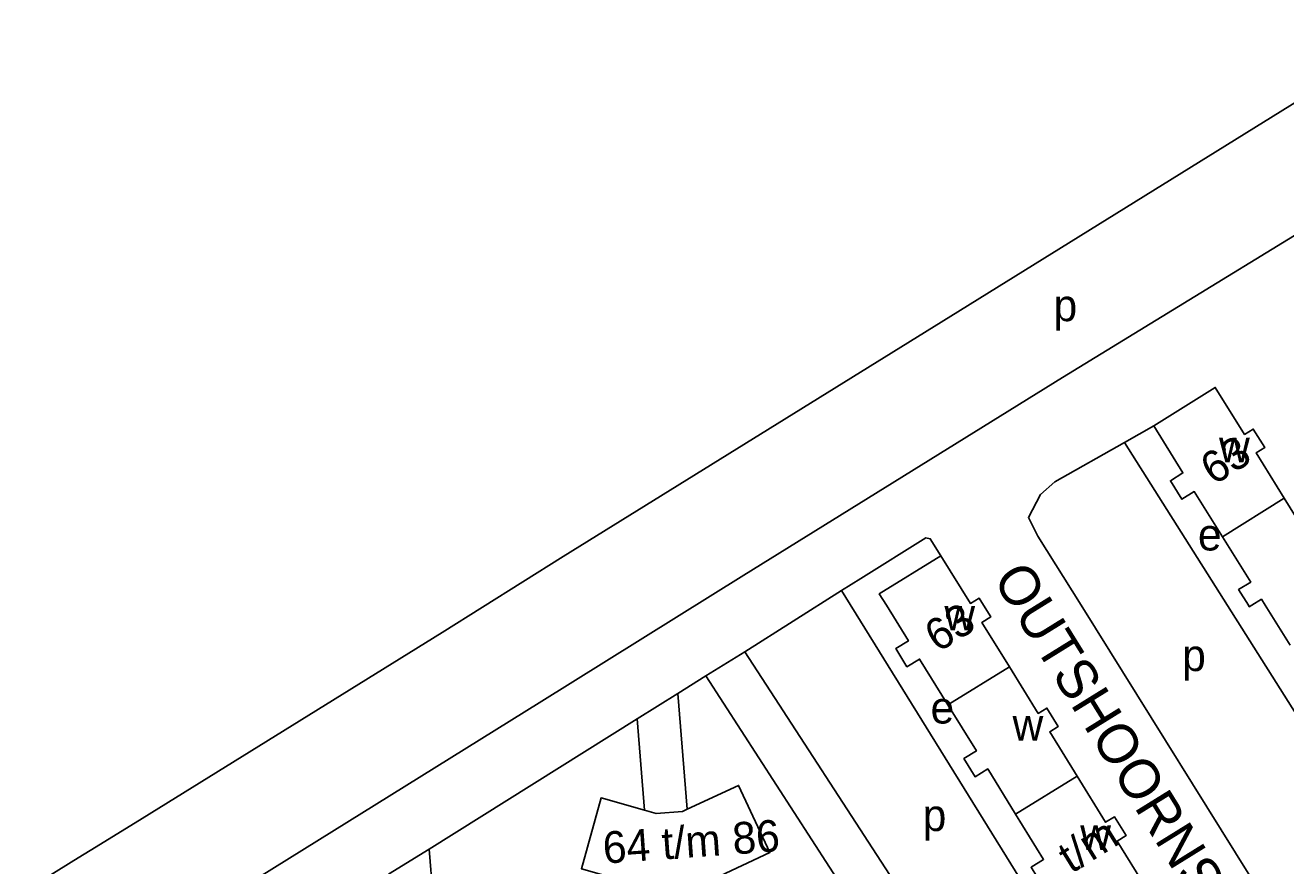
# Model space of a CAD drawing. Extents: x 159294 to 161936, y 384538 to 386517.
# Drawn here: x 160068.5 to 160227.2, y 386133.9 to 386239.7 of the extents above; entities that cross this region are included whole.
import ezdxf

# ---------------------------------------------------------------- set-up
doc = ezdxf.new("R2010")
doc.units = 0
for name, color, linetype in [('BLT_Basislijn', 7, 'Continuous'), ('BLT_Bebouwing', 7, 'Continuous'), ('BLT_Centroide', 7, 'Continuous'), ('BLT_Huisnummer_reeks', 7, 'Continuous'), ('BLT_Onderverdeling_panden', 7, 'Continuous'), ('BLT_Straatnaam', 7, 'Continuous')]:
    doc.layers.add(name, color=color, linetype=linetype)

msp = doc.modelspace()

# ---------------------------------------------------------------- linework, layer by layer
at = {"layer": 'BLT_Basislijn'}
for p, q in [((160206.88, 386187.16), (160243.71, 386128.83)), ((160171.29, 386168.51), (160209.94, 386106.13)), ((160121.03, 386163.25), (160083.26, 386139.84)), ((160159.1, 386160.81), (160154.21, 386157.79)), ((160159.1, 386160.81), (160182.3, 386125.13)), ((160150.67, 386155.55), (160154.21, 386157.79)), ((160154.21, 386157.79), (160177.14, 386122.35)), ((160150.67, 386155.55), (160145.55, 386152.35)), ((160151.86, 386140.99), (160150.67, 386155.55)), ((160145.55, 386152.35), (160119.37, 386135.95)), ((160145.55, 386152.35), (160146.5, 386140.86)), ((160083.26, 386139.84), (160078.01, 386136.59)), ((160078.01, 386136.59), (160074.68, 386134.53)), ((160114.28, 386132.8), (160119.37, 386135.95)), ((160119.37, 386135.95), (160120.59, 386121.43)), ((160074.68, 386134.53), (160068.54, 386130.73))]:
    msp.add_line(p, q, dxfattribs=at)
for points in [[(160244.05, 386239.67), (160185.05, 386203.05), (160136.24, 386172.78), (160121.03, 386163.25)], [(160244.21, 386222.95), (160199.09, 386195.35), (160158.97, 386170.44), (160133.23, 386154.38)], [(160210.57, 386189.25), (160206.88, 386187.16)], [(160206.88, 386187.16), (160198.13, 386182.19), (160196.34, 386180.6), (160194.8, 386177.7), (160196.01, 386175.37), (160201.44, 386166.67), (160226.09, 386127.17), (160229.41, 386122.44), (160230.3, 386121.71), (160233.26, 386121.98), (160243.71, 386128.83)], [(160183.8, 386172.89), (160182.46, 386175.04), (160181.91, 386175.14), (160173.71, 386170.03), (160171.29, 386168.51)], [(160171.29, 386168.51), (160159.1, 386160.81)], [(160133.23, 386154.38), (160088.61, 386126.62), (160076.91, 386119.1), (160076.55, 386118.35)]]:
    msp.add_lwpolyline(points, dxfattribs=at)
at = {"layer": 'BLT_Bebouwing'}
for points in [[(160227.01, 386180.13), (160223.46, 386185.83), (160224.55, 386186.5), (160223.1, 386188.83), (160222.02, 386188.16), (160218.33, 386194.09), (160210.57, 386189.25)], [(160210.57, 386189.25), (160214.26, 386183.33), (160212.68, 386182.34), (160214.13, 386180.01), (160215.68, 386180.98), (160219.24, 386175.28)], [(160235.54, 386166.49), (160235.43, 386166.67), (160231.94, 386172.27), (160232.97, 386172.91), (160231.62, 386175.06), (160230.58, 386174.41), (160227.01, 386180.13)], [(160219.24, 386175.28), (160222.79, 386169.58), (160221.26, 386168.63), (160222.49, 386166.67), (160222.61, 386166.47), (160222.92, 386166.67), (160224.14, 386167.42), (160224.61, 386166.67), (160227.74, 386161.63)], [(160184.68, 386154.12), (160181.11, 386159.9), (160179.52, 386158.92), (160178.11, 386161.21), (160179.7, 386162.18), (160176.93, 386166.67), (160176.04, 386168.09), (160183.8, 386172.89)], [(160192.43, 386158.91), (160188.96, 386164.51), (160190.07, 386165.19), (160189.15, 386166.67), (160188.6, 386167.57), (160187.5, 386166.89), (160183.8, 386172.89)], [(160200.95, 386145.15), (160197.49, 386150.75), (160198.56, 386151.41), (160197.13, 386153.73), (160196.04, 386153.05), (160192.43, 386158.91)], [(160184.68, 386154.12), (160188.26, 386148.34), (160186.68, 386147.37), (160188.1, 386145.08), (160189.68, 386146.06), (160193.2, 386140.36)], [(160209.46, 386131.36), (160205.99, 386136.99), (160207.1, 386137.67), (160205.63, 386140.05), (160204.52, 386139.36), (160200.95, 386145.15)], [(160151.86, 386140.99), (160158.32, 386143.99), (160162.27, 386135.53), (160155.31, 386132.28), (160155.91, 386124.48), (160152.7, 386124.24), (160153.54, 386113.58), (160143.63, 386112.88), (160142.77, 386123.45), (160146.54, 386123.76), (160145.92, 386131.4), (160138.54, 386133.5), (160141.03, 386142.42), (160146.5, 386140.86)], [(160146.5, 386140.86), (160147.95, 386140.45), (160151.26, 386140.72), (160151.86, 386140.99)], [(160193.2, 386140.36), (160196.72, 386134.67), (160195.14, 386133.69), (160196.58, 386131.35), (160198.17, 386132.33), (160201.72, 386126.58)]]:
    msp.add_lwpolyline(points, dxfattribs=at)
at = {"layer": 'BLT_Onderverdeling_panden'}
for p, q in [((160219.24, 386175.28), (160227.01, 386180.13)), ((160184.68, 386154.12), (160192.43, 386158.91)), ((160193.2, 386140.36), (160200.95, 386145.15))]:
    msp.add_line(p, q, dxfattribs=at)

# ---------------------------------------------------------------- texts
at = {"layer": 'BLT_Centroide'}
for s, p in [('p', (160197.97, 386202.42)), ('w', (160218.8, 386184.67)), ('e', (160216.14, 386173.56)), ('w', (160184.23, 386163.52)), ('p', (160214.16, 386158.38)), ('e', (160182.49, 386151.78)), ('w', (160192.81, 386149.64)), ('p', (160181.5, 386138.25)), ('w', (160201.33, 386135.88))]:
    msp.add_text(s, height=4, dxfattribs=at).set_placement(p)
at = {"layer": 'BLT_Huisnummer_reeks'}
for s, rotation, p in [('63', 31.9351, (160218.12, 386181.7)), ('63', 31.7213, (160183.39, 386160.65)), ('64 t/m 86', 4.0626, (160141.38, 386134.14)), ('t/m', 31.7213, (160200.19, 386132.83))]:
    msp.add_text(s, height=4, rotation=rotation, dxfattribs=at).set_placement(p)
at = {"layer": 'BLT_Straatnaam'}
msp.add_text('OUTSHOORNSTRAAT', height=5, rotation=301.7946, dxfattribs=at).set_placement((160190.24, 386170.01))

doc.saveas('drawing.dxf')
